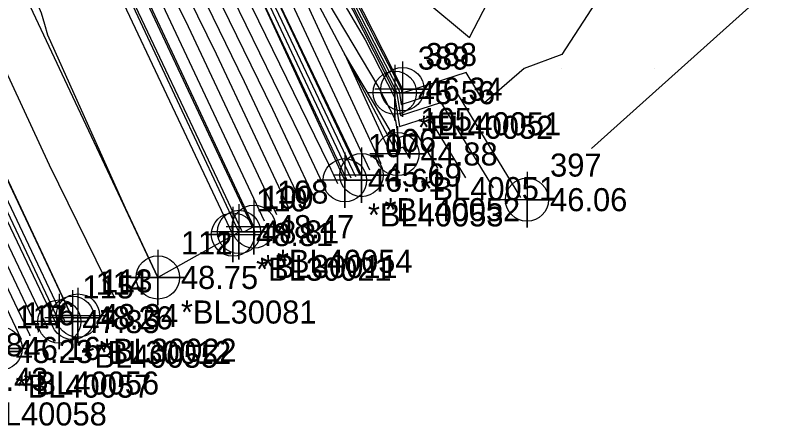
# Model space of a CAD drawing. Extents: x 2090860 to 2091277, y 159470 to 160080.
# Drawn here: x 2091170.8 to 2091253, y 159481.3 to 159525.8 of the extents above; entities that cross this region are included whole.
import ezdxf

# ---------------------------------------------------------------- set-up
doc = ezdxf.new("R2010")
doc.units = 0
for name, color, linetype in [('DTM Contours Major', 7, 'Continuous'), ('DTM Contours Minor', 7, 'Continuous'), ('Exist DTM Breakline', 7, 'Continuous'), ('Exist DTM Breakline Cogo Comment', 7, 'Continuous'), ('Exist DTM Breakline Cogo Elevation', 7, 'Continuous'), ('Exist DTM Breakline Cogo Number', 7, 'Continuous'), ('Exist DTM Breakline Cogo Point CELL', 7, 'Continuous'), ('Exist DTM Crownline', 7, 'Continuous'), ('Exist DTM Crownline Cogo Comment', 7, 'Continuous'), ('Exist DTM Crownline Cogo Elevation', 7, 'Continuous'), ('Exist DTM Crownline Cogo Number', 7, 'Continuous'), ('Exist DTM Crownline Cogo Point CELL', 7, 'Continuous'), ('Exist DTM QL2 LIDAR Elevation Point', 7, 'Continuous'), ('Exist DTM Regular Point CELL', 7, 'Continuous'), ('Exist DTM Regular Point Cogo Elevation', 7, 'Continuous'), ('Exist DTM Regular Point Cogo Number', 7, 'Continuous'), ('Exist Roads EOP', 7, 'Continuous'), ('Exist Roads EOP Cogo Comment', 7, 'Continuous'), ('Exist Roads EOP Cogo Elevation', 7, 'Continuous'), ('Exist Roads EOP Cogo Number', 7, 'Continuous'), ('Exist Roads EOP Cogo Point CELL', 7, 'Continuous'), ('Exist Roads EOT', 7, 'Continuous'), ('Exist Roads EOT Cogo Comment', 7, 'Continuous'), ('Exist Roads EOT Cogo Elevation', 7, 'Continuous'), ('Exist Roads EOT Cogo Number', 7, 'Continuous'), ('Exist Roads EOT Cogo Point CELL', 7, 'Continuous')]:
    doc.layers.add(name, color=color, linetype=linetype)

msp = doc.modelspace()

# ---------------------------------------------------------------- linework, layer by layer
at = {"layer": 'DTM Contours Major'}
for points in [[(2091162.224, 159619.585), (2091172.872, 159598.824), (2091175.683, 159592.701), (2091177.053, 159590.039), (2091177.994, 159587.927), (2091182.697, 159577.853), (2091190.683, 159560.736), (2091193.182, 159555.38), (2091195.125, 159551.216), (2091203.298, 159535.129), (2091208.815, 159524.502), (2091210.513, 159521.162), (2091212.364, 159517.603), (2091212.599, 159516.124), (2091218.269, 159517.951), (2091225.533, 159506.041)], [(2091207.678, 159508.272), (2091198.697, 159527.234), (2091194.865, 159535.399), (2091190.69, 159544.208), (2091188.733, 159548.38), (2091177.66, 159572.236), (2091176.092, 159575.54), (2091172.141, 159584.119), (2091172.098, 159584.209), (2091171.958, 159584.503), (2091159.156, 159611.268)], [(2091204.414, 159506.84), (2091201.716, 159512.582), (2091191.366, 159533.837), (2091186.841, 159543.131), (2091185.01, 159547.028), (2091175.432, 159567.857), (2091172.415, 159574.212), (2091169.375, 159580.835)], [(2091199.122, 159504.143), (2091189.543, 159524.53), (2091186.274, 159531.245), (2091184.844, 159534.181), (2091179.739, 159545.048), (2091176.735, 159551.582), (2091166.955, 159572.179)], [(2091252.964, 159549.201), (2091248.255, 159545.987), (2091250.644, 159538.935), (2091243.198, 159530.914), (2091251.293, 159527.588), (2091233.2, 159511.353)], [(2091213.581, 159510.253), (2091212.821, 159511.501), (2091212.227, 159511.309), (2091212.133, 159511.897), (2091211.524, 159513.093), (2091206.461, 159521.579), (2091209.883, 159514.133), (2091211.616, 159510.413)], [(2091163.21, 159519.856), (2091171.585, 159502.289), (2091176.091, 159492.742), (2091176.031, 159492.59)], [(2091166.043, 159504.368), (2091172.359, 159491.131), (2091172.312, 159491.01)]]:
    msp.add_lwpolyline(points, dxfattribs=at)
at = {"layer": 'DTM Contours Minor'}
for points in [[(2091161.719, 159619.417), (2091174.621, 159594.26), (2091175.344, 159592.685), (2091177.593, 159588.317), (2091177.814, 159587.82), (2091178.922, 159585.448), (2091190.498, 159560.635), (2091194.121, 159552.871), (2091194.924, 159551.15), (2091206.182, 159528.988), (2091208.556, 159524.417), (2091211.295, 159519.027), (2091212.099, 159517.481), (2091212.506, 159514.92), (2091216.907, 159516.339), (2091222.545, 159507.094)], [(2091219.632, 159519.564), (2091212.693, 159517.327), (2091212.629, 159517.725), (2091209.731, 159523.297), (2091209.075, 159524.588), (2091200.413, 159541.27), (2091195.327, 159551.282), (2091192.243, 159557.89), (2091190.868, 159560.838), (2091186.473, 159570.258), (2091178.174, 159588.034), (2091176.514, 159591.761), (2091176.021, 159592.717), (2091171.123, 159603.387), (2091162.729, 159619.754)], [(2091208.167, 159508.426), (2091195.493, 159535.185), (2091195.333, 159535.526), (2091192.741, 159540.994), (2091189.374, 159548.228), (2091189.229, 159548.545), (2091188.884, 159549.244), (2091176.928, 159575.875), (2091175.903, 159577.989), (2091172.908, 159584.624), (2091161.198, 159608.686)], [(2091206.699, 159507.964), (2091205.104, 159511.333), (2091194.504, 159533.918), (2091193.912, 159535.133), (2091187.839, 159547.606), (2091187.646, 159548.017), (2091181.102, 159562.249), (2091174.971, 159575.16), (2091174.588, 159575.994), (2091170.957, 159583.654), (2091159.144, 159608.415)], [(2091168.282, 159602.906), (2091175.112, 159590.435), (2091176.802, 159587.073), (2091178.205, 159583.849), (2091187.638, 159564.48), (2091190.823, 159556.883), (2091193.941, 159550.68), (2091195.402, 159548.574), (2091206.766, 159526.374), (2091208.705, 159523.123), (2091211.92, 159516.816), (2091212.413, 159513.716), (2091215.545, 159514.726), (2091219.557, 159508.147)], [(2091209.191, 159508.992), (2091200.054, 159528.609), (2091196.536, 159536.262), (2091193.163, 159543.51), (2091190.602, 159549.103), (2091184.496, 159561.462), (2091177.854, 159576.258), (2091175.47, 159581.171), (2091173.723, 159585.042), (2091166.893, 159599.078)], [(2091207.188, 159508.118), (2091201.9, 159519.283), (2091194.397, 159535.271), (2091192.331, 159539.631), (2091188.293, 159548.241), (2091183.497, 159558.573), (2091175.532, 159575.35), (2091173.365, 159580.056), (2091171.528, 159583.932), (2091165.551, 159596.459)], [(2091205.737, 159507.515), (2091204.759, 159509.595), (2091192.639, 159534.485), (2091187.34, 159545.368), (2091186.328, 159547.522), (2091175.106, 159571.926), (2091173.78, 159574.721), (2091170.214, 159582.489)], [(2091203.091, 159506.166), (2091198.673, 159515.569), (2091190.093, 159533.189), (2091186.342, 159540.893), (2091183.692, 159546.533), (2091175.758, 159563.789), (2091171.05, 159573.704), (2091168.536, 159579.18)], [(2091201.768, 159505.492), (2091195.63, 159518.556), (2091188.82, 159532.541), (2091185.842, 159538.656), (2091182.375, 159546.038), (2091176.083, 159559.72), (2091169.685, 159573.196)], [(2091200.445, 159504.817), (2091192.587, 159521.543), (2091187.547, 159531.893), (2091185.343, 159536.418), (2091181.057, 159545.543), (2091176.409, 159555.651), (2091168.32, 159572.687)], [(2091197.799, 159503.468), (2091186.5, 159527.517), (2091185.001, 159530.597), (2091184.345, 159531.943), (2091178.421, 159544.554), (2091177.06, 159547.513), (2091165.59, 159571.671)], [(2091195.553, 159502.303), (2091196.439, 159502.8), (2091196.494, 159502.824), (2091185.126, 159527.038), (2091183.736, 159529.981), (2091177.961, 159542.279), (2091177.132, 159544.034), (2091175.382, 159547.738), (2091164.281, 159571.137)], [(2091186.268, 159497.394), (2091194.797, 159502.179), (2091195.322, 159502.407), (2091193.005, 159507.342), (2091182.517, 159529.546), (2091181.63, 159531.436), (2091175.982, 159543.393), (2091164.057, 159568.636)], [(2091163.189, 159550.122), (2091173.592, 159526.022), (2091173.938, 159524.793), (2091174.26, 159523.652), (2091182.682, 159504.914), (2091186.184, 159497.423), (2091186.212, 159497.365)], [(2091216.569, 159509.2), (2091214.183, 159513.113), (2091212.32, 159512.513), (2091212.026, 159514.357), (2091210.114, 159518.108), (2091200.265, 159534.617), (2091197.498, 159540.025), (2091194.233, 159544.729), (2091196.952, 159538.791), (2091197.774, 159537.026), (2091204.968, 159521.371), (2091210.403, 159509.703)], [(2091215.045, 159527.533), (2091220, 159523.348), (2091223.416, 159530)], [(2091235.501, 159530), (2091230, 159521.526), (2091225.919, 159520), (2091221.621, 159516.302), (2091219.632, 159519.564)], [(2091168.569, 159522.204), (2091174.475, 159509.571), (2091181.534, 159495.15)], [(2091165.094, 159518.136), (2091176.963, 159492.989), (2091176.961, 159492.985)], [(2091163.243, 159517.465), (2091175.191, 159492.424), (2091175.101, 159492.195)], [(2091164.176, 159513.099), (2091174.247, 159491.993), (2091174.172, 159491.8)], [(2091165.11, 159508.734), (2091173.303, 159491.562), (2091173.242, 159491.405)], [(2091166.977, 159500.002), (2091171.415, 159490.7), (2091171.382, 159490.616)]]:
    msp.add_lwpolyline(points, dxfattribs=at)
at = {"layer": 'Exist DTM Breakline'}
for points in [[(2091212.183, 159510.746), (2091191.689, 159549.546), (2091174.865, 159585.627), (2091158.431, 159619.302), (2091139.416, 159656.456), (2091124.853, 159687.366), (2091111.104, 159719.28), (2091102.676, 159740.8), (2091098.872, 159752.926), (2091092.871, 159757.669)], [(2091196.63, 159502.872), (2091177.33, 159544.144), (2091161.139, 159578.46), (2091145.393, 159612.39), (2091128.083, 159650.689), (2091112.842, 159682.377), (2091098.521, 159713.445), (2091088.424, 159738.261), (2091087.489, 159747.73)], [(2091104.06, 159746.702), (2091118.019, 159713.353), (2091131.537, 159686.371), (2091144.554, 159657.113), (2091164.611, 159620.381), (2091178.178, 159588.037), (2091195.659, 159551.391), (2091212.727, 159517.77)], [(2091103.084, 159746.105), (2091115.591, 159711.787), (2091128.144, 159684.602), (2091142.549, 159655.707), (2091161.438, 159619.323), (2091177.759, 159587.787), (2091194.782, 159551.104), (2091211.895, 159517.387)], [(2091206.488, 159507.898), (2091187.957, 159548.134), (2091170.754, 159583.555), (2091154.779, 159617.345), (2091136.615, 159654.772), (2091121.985, 159686.47), (2091108.438, 159717.464), (2091100.122, 159738.875)], [(2091175.557, 159492.591), (2091156.216, 159533.598), (2091139.639, 159569.307), (2091124.335, 159601.659), (2091105.938, 159640.92), (2091091.734, 159670.471), (2091076.451, 159703.516), (2091059.361, 159735)], [(2091208.294, 159508.466), (2091189.147, 159548.511), (2091172.112, 159584.216), (2091156.469, 159618.152), (2091137.831, 159655.463)]]:
    msp.add_lwpolyline(points, dxfattribs=at)
at = {"layer": 'Exist DTM Breakline Cogo Point CELL'}
for points in [[(2091212.727, 159520.77), (2091212.727, 159514.77), (2091212.727, 159517.77), (2091215.727, 159517.77), (2091209.727, 159517.77)], [(2091211.895, 159520.387), (2091211.895, 159514.387), (2091211.895, 159517.387), (2091214.895, 159517.387), (2091208.895, 159517.387)], [(2091212.183, 159513.746), (2091212.183, 159507.746), (2091212.183, 159510.746), (2091215.183, 159510.746), (2091209.183, 159510.746)], [(2091208.294, 159511.466), (2091208.294, 159505.466), (2091208.294, 159508.466), (2091211.294, 159508.466), (2091205.294, 159508.466)], [(2091206.488, 159510.898), (2091206.488, 159504.898), (2091206.488, 159507.898), (2091209.488, 159507.898), (2091203.488, 159507.898)], [(2091196.63, 159505.872), (2091196.63, 159499.872), (2091196.63, 159502.872), (2091199.63, 159502.872), (2091193.63, 159502.872)], [(2091175.557, 159495.591), (2091175.557, 159489.591), (2091175.557, 159492.591), (2091178.557, 159492.591), (2091172.557, 159492.591)], [(2091169.184, 159492.682), (2091169.184, 159486.682), (2091169.184, 159489.682), (2091172.184, 159489.682), (2091166.184, 159489.682)], [(2091168.326, 159492.347), (2091168.326, 159486.347), (2091168.326, 159489.347), (2091171.326, 159489.347), (2091165.326, 159489.347)]]:
    msp.add_lwpolyline(points, dxfattribs=at)
for centre in [(2091211.895, 159517.387), (2091212.727, 159517.77), (2091212.183, 159510.746), (2091208.294, 159508.466), (2091206.488, 159507.898), (2091196.63, 159502.872), (2091175.557, 159492.591), (2091169.184, 159489.682)]:
    msp.add_circle(centre, 2.344, dxfattribs=at)
at = {"layer": 'Exist DTM Crownline'}
msp.add_lwpolyline([(2091186.231, 159497.374), (2091150.267, 159573.786), (2091135.077, 159606.786), (2091117.269, 159645.439), (2091102.614, 159676.949), (2091088.105, 159708.377), (2091072.916, 159741.265)], dxfattribs=at)
at = {"layer": 'Exist DTM Crownline Cogo Point CELL'}
msp.add_lwpolyline([(2091186.231, 159500.374), (2091186.231, 159494.374), (2091186.231, 159497.374), (2091189.231, 159497.374), (2091183.231, 159497.374)], dxfattribs=at)
msp.add_circle((2091186.231, 159497.374), 2.344, dxfattribs=at)
at = {"layer": 'Exist DTM QL2 LIDAR Elevation Point'}
for p, q in [((2091220, 159520), (2091220, 159520)), ((2091230, 159520), (2091230, 159520)), ((2091240, 159520), (2091240, 159520))]:
    msp.add_line(p, q, dxfattribs=at)
at = {"layer": 'Exist DTM Regular Point CELL'}
msp.add_lwpolyline([(2091226.226, 159508.797), (2091226.226, 159502.797), (2091226.226, 159505.797), (2091229.226, 159505.797), (2091223.226, 159505.797)], dxfattribs=at)
msp.add_circle((2091226.226, 159505.797), 2.344, dxfattribs=at)
at = {"layer": 'Exist Roads EOP'}
for points in [[(2091195.022, 159502.3), (2091175.816, 159543.301), (2091159.602, 159577.847), (2091143.942, 159611.542), (2091126.198, 159649.797), (2091111.241, 159681.734), (2091096.716, 159712.783), (2091082.116, 159745.373)], [(2091176.987, 159492.996), (2091157.634, 159534.321), (2091140.802, 159570.232), (2091125.679, 159602.447), (2091107.654, 159641.501), (2091093.369, 159671.636), (2091078.486, 159704.356), (2091063.606, 159736.869)]]:
    msp.add_lwpolyline(points, dxfattribs=at)
at = {"layer": 'Exist Roads EOP Cogo Point CELL'}
for points in [[(2091195.022, 159505.3), (2091195.022, 159499.3), (2091195.022, 159502.3), (2091198.022, 159502.3), (2091192.022, 159502.3)], [(2091176.987, 159495.996), (2091176.987, 159489.996), (2091176.987, 159492.996), (2091179.987, 159492.996), (2091173.987, 159492.996)]]:
    msp.add_lwpolyline(points, dxfattribs=at)
for centre in [(2091195.022, 159502.3), (2091176.987, 159492.996)]:
    msp.add_circle(centre, 2.344, dxfattribs=at)
at = {"layer": 'Exist Roads EOT'}
msp.add_lwpolyline([(2091194.37, 159502.018), (2091175.119, 159542.803), (2091158.987, 159577.703), (2091143.368, 159611.224), (2091125.349, 159649.375), (2091110.434, 159681.3), (2091096.012, 159712.514), (2091081.141, 159744.981)], dxfattribs=at)
at = {"layer": 'Exist Roads EOT Cogo Point CELL'}
for points in [[(2091194.37, 159505.018), (2091194.37, 159499.018), (2091194.37, 159502.018), (2091191.37, 159502.018), (2091197.37, 159502.018)], [(2091186.231, 159500.374), (2091186.231, 159494.374), (2091186.231, 159497.374), (2091183.231, 159497.374), (2091189.231, 159497.374)], [(2091177.573, 159496.241), (2091177.573, 159490.241), (2091177.573, 159493.241), (2091174.573, 159493.241), (2091180.573, 159493.241)]]:
    msp.add_lwpolyline(points, dxfattribs=at)
for centre in [(2091194.37, 159502.018), (2091186.231, 159497.374), (2091177.573, 159493.241)]:
    msp.add_circle(centre, 2.344, dxfattribs=at)

# ---------------------------------------------------------------- texts
at = {"layer": 'Exist DTM Breakline Cogo Comment'}
for s, p in [('*EL40052', (2091214.395, 159512.387)), ('*EL40051', (2091215.227, 159512.77)), ('*BL40051', (2091214.683, 159505.746)), ('*BL40052', (2091210.794, 159503.466)), ('*BL40053', (2091208.988, 159502.898)), ('*BL40054', (2091199.13, 159497.872)), ('*BL40055', (2091178.057, 159487.591)), ('*BL40057', (2091170.826, 159484.347)), ('*BL40056', (2091171.684, 159484.682)), ('*BL40058', (2091166.014, 159481.332))]:
    msp.add_text(s, height=2.5, dxfattribs=at).set_placement(p)
at = {"layer": 'Exist DTM Breakline Cogo Elevation'}
for s, p in [('46.34', (2091215.227, 159516.52)), ('45.56', (2091214.395, 159516.137)), ('44.88', (2091214.683, 159509.496)), ('46.61', (2091208.988, 159506.648)), ('45.69', (2091210.794, 159507.216)), ('48.47', (2091199.13, 159501.622)), ('47.85', (2091178.057, 159491.341)), ('46.16', (2091171.684, 159488.432)), ('45.23', (2091170.826, 159488.097)), ('44.43', (2091166.014, 159485.082))]:
    msp.add_text(s, height=2.5, dxfattribs=at).set_placement(p)
at = {"layer": 'Exist DTM Breakline Cogo Number'}
for s, p in [('389', (2091214.395, 159519.887)), ('388', (2091215.227, 159520.27)), ('105', (2091214.683, 159513.246)), ('106', (2091210.794, 159510.966)), ('107', (2091208.988, 159510.398)), ('108', (2091199.13, 159505.372)), ('115', (2091178.057, 159495.091)), ('117', (2091170.826, 159491.847)), ('116', (2091171.684, 159492.182)), ('118', (2091166.014, 159488.832))]:
    msp.add_text(s, height=2.5, dxfattribs=at).set_placement(p)
at = {"layer": 'Exist DTM Crownline Cogo Comment'}
msp.add_text('*BL30081', height=2.5, dxfattribs=at).set_placement((2091188.731, 159492.374))
at = {"layer": 'Exist DTM Crownline Cogo Elevation'}
msp.add_text('48.75', height=2.5, dxfattribs=at).set_placement((2091188.731, 159496.124))
at = {"layer": 'Exist DTM Crownline Cogo Number'}
msp.add_text('112', height=2.5, dxfattribs=at).set_placement((2091188.731, 159499.874))
at = {"layer": 'Exist DTM Regular Point Cogo Elevation'}
msp.add_text('46.06', height=2.5, dxfattribs=at).set_placement((2091228.726, 159504.547))
at = {"layer": 'Exist DTM Regular Point Cogo Number'}
msp.add_text('397', height=2.5, dxfattribs=at).set_placement((2091228.726, 159508.297))
at = {"layer": 'Exist Roads EOP Cogo Comment'}
for s, p in [('*BL30011', (2091197.522, 159497.3)), ('*BL30012', (2091179.487, 159487.996))]:
    msp.add_text(s, height=2.5, dxfattribs=at).set_placement(p)
at = {"layer": 'Exist Roads EOP Cogo Elevation'}
for s, p in [('48.81', (2091197.522, 159501.05)), ('48.26', (2091179.487, 159491.746))]:
    msp.add_text(s, height=2.5, dxfattribs=at).set_placement(p)
at = {"layer": 'Exist Roads EOP Cogo Number'}
for s, p in [('109', (2091197.522, 159504.8)), ('114', (2091179.487, 159495.496))]:
    msp.add_text(s, height=2.5, dxfattribs=at).set_placement(p)
at = {"layer": 'Exist Roads EOT Cogo Comment'}
for s, p in [('*BL30021', (2091196.87, 159497.018)), ('*BL30022', (2091180.073, 159488.241))]:
    msp.add_text(s, height=2.5, dxfattribs=at).set_placement(p)
at = {"layer": 'Exist Roads EOT Cogo Elevation'}
for s, p in [('48.81', (2091196.87, 159500.768)), ('48.75', (2091188.731, 159496.124)), ('48.34', (2091180.073, 159491.991))]:
    msp.add_text(s, height=2.5, dxfattribs=at).set_placement(p)
at = {"layer": 'Exist Roads EOT Cogo Number'}
for s, p in [('110', (2091196.87, 159504.518)), ('111', (2091188.731, 159499.874)), ('113', (2091180.073, 159495.741))]:
    msp.add_text(s, height=2.5, dxfattribs=at).set_placement(p)

doc.saveas('drawing.dxf')
